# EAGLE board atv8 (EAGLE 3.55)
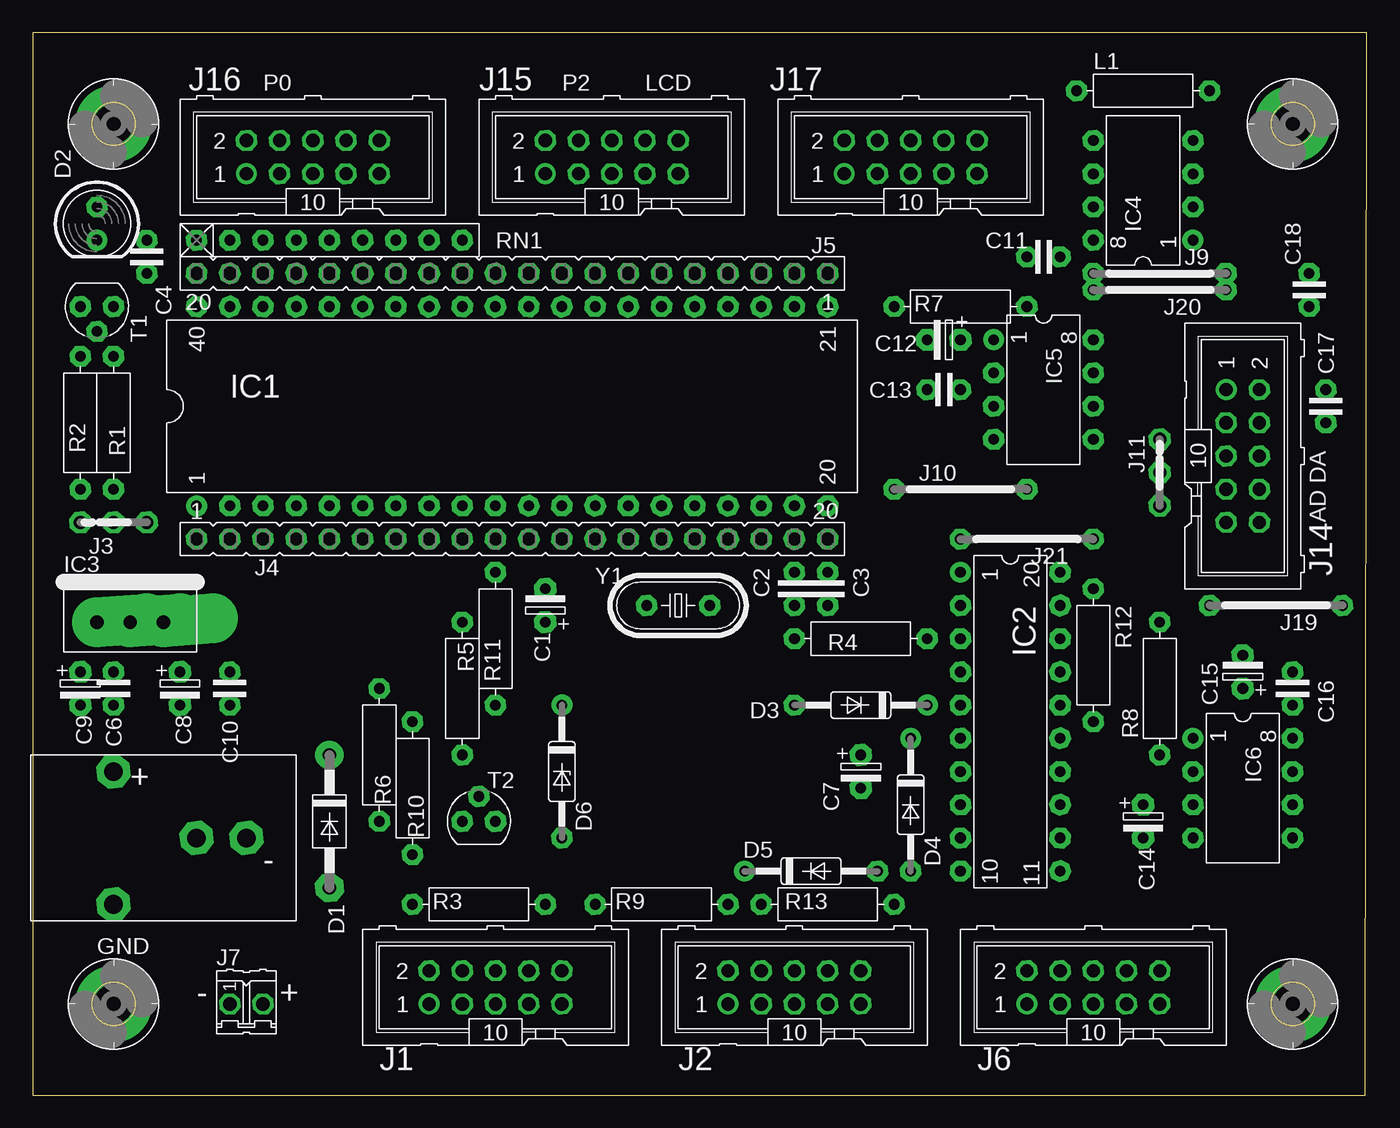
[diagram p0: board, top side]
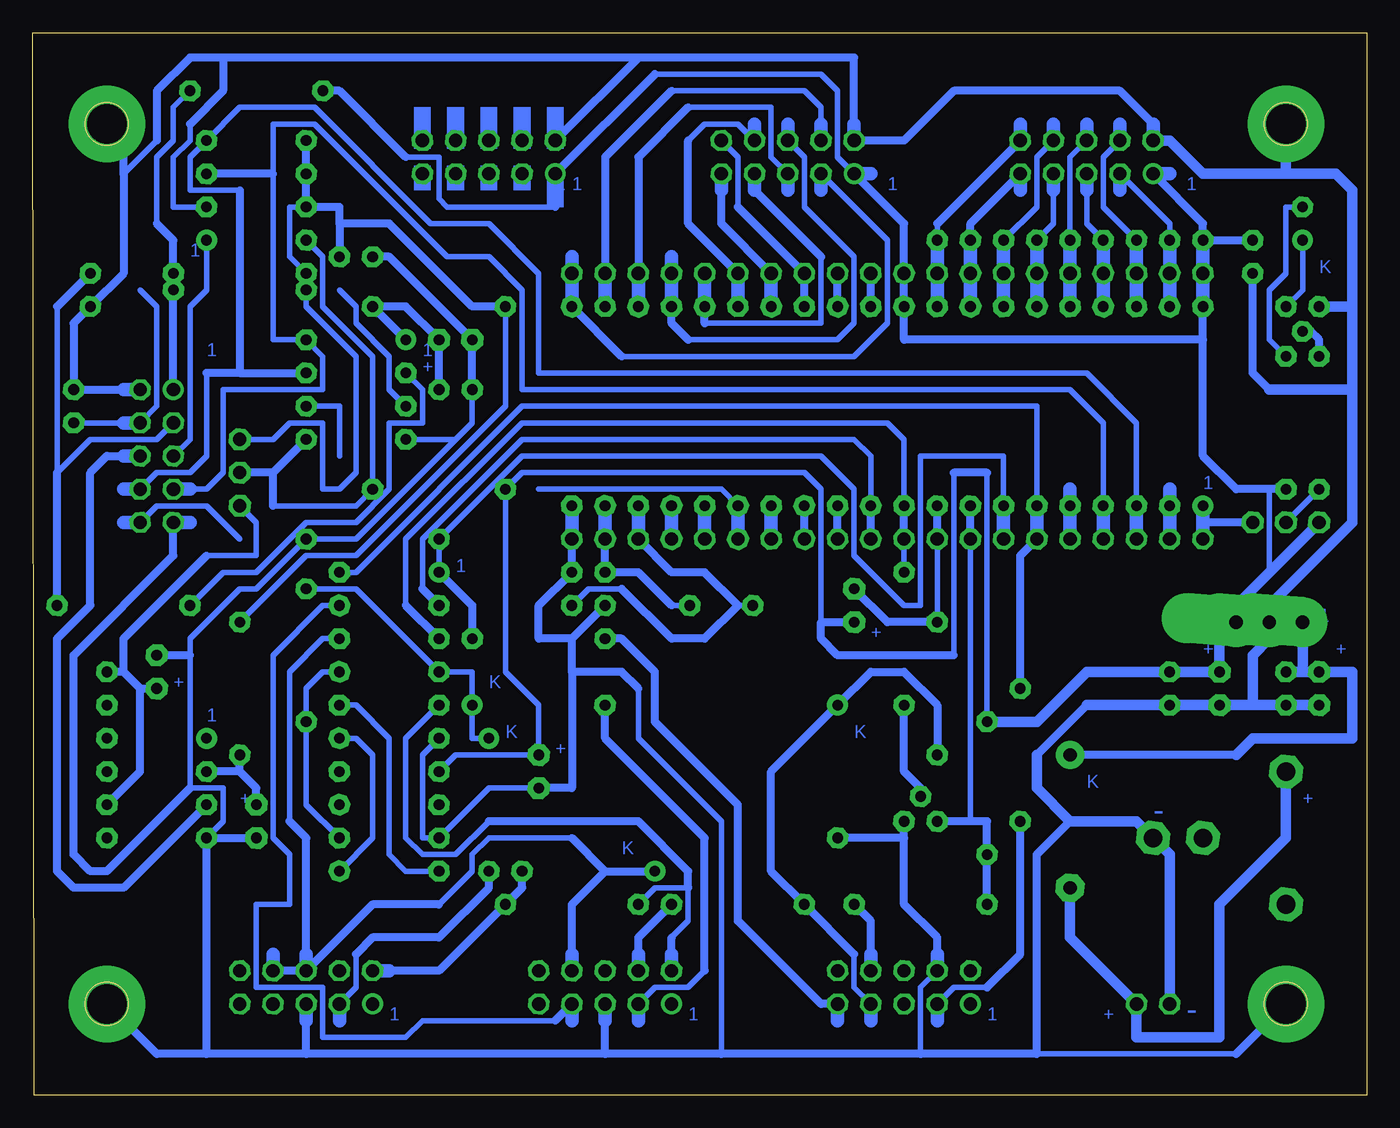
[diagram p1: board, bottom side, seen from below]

Size 102.03 x 81.27 mm. Coordinates in mm from the lower left corner, seen from the top.
Outline: 0,0 101.91,0 102.03,81.27 0,81.27 0,0
Copper layers used: Bottom

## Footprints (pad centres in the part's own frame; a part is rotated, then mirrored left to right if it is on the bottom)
-2,5 = drill 0.813 pad 1.676 octagon:  -1.27,0;  1.27,0
2,5 = drill 0.813 pad 1.6 octagon:  -1.27,0;  1.27,0
41-10 = drill 1.016 pad 2.159 octagon:  5.08,0 | drill 1.016 pad 2.159 round:  -5.08,0
D5 = drill 0.813 pad 1.6 octagon:  -1.27,0 | drill 0.813 pad 1.6 round:  1.27,0
35-10 = drill 0.813 pad 1.6 round:  -5.08,0 | drill 0.813 pad 1.6 octagon:  5.08,0
35Z10 = drill 0.813 pad 1.6 round:  -5.08,0 | drill 0.813 pad 1.6 octagon:  5.08,0
L40 = drill 0.813 pad 1.6 round:  -24.13,-7.62 | drill 0.813 pad 1.6 octagon:  -21.59,-7.62;  -19.05,-7.62;  -16.51,-7.62;  -13.97,-7.62;  -11.43,-7.62;  -8.89,-7.62;  -6.35,-7.62;  -3.81,-7.62;  -1.27,-7.62;  1.27,-7.62;  3.81,-7.62;  6.35,-7.62;  8.89,-7.62;  11.43,-7.62;  13.97,-7.62;  16.51,-7.62;  19.05,-7.62;  21.59,-7.62;  24.13,-7.62;  24.13,7.62;  21.59,7.62;  19.05,7.62;  16.51,7.62;  13.97,7.62;  11.43,7.62;  8.89,7.62;  6.35,7.62;  3.81,7.62;  1.27,7.62;  -1.27,7.62;  -3.81,7.62;  -6.35,7.62;  -8.89,7.62;  -11.43,7.62;  -13.97,7.62;  -16.51,7.62;  -19.05,7.62;  -21.59,7.62;  -24.13,7.62
L20 = drill 0.813 pad 1.6 round:  -11.43,-3.81 | drill 0.813 pad 1.6 octagon:  -8.89,-3.81;  -6.35,-3.81;  -3.81,-3.81;  -1.27,-3.81;  1.27,-3.81;  3.81,-3.81;  6.35,-3.81;  8.89,-3.81;  11.43,-3.81;  11.43,3.81;  8.89,3.81;  6.35,3.81;  3.81,3.81;  1.27,3.81;  -1.27,3.81;  -3.81,3.81;  -6.35,3.81;  -8.89,3.81;  -11.43,3.81
220 = drill 1.016 pad 3.81 offset:  -2.54,0;  0,0;  2.54,0
L08 = drill 0.813 pad 1.6 round:  -3.81,-3.81 | drill 0.813 pad 1.6 octagon:  -1.27,-3.81;  1.27,-3.81;  3.81,-3.81;  3.81,3.81;  1.27,3.81;  -1.27,3.81;  -3.81,3.81
10 = drill 1.016 pad 1.6 round:  -5.08,-1.27 | drill 1.016 pad 1.6 octagon:  -5.08,1.27;  -2.54,-1.27;  -2.54,1.27;  0,-1.27;  0,1.27;  2.54,-1.27;  2.54,1.27;  5.08,-1.27;  5.08,1.27
C = drill 1.016 pad 1.676 octagon:  -5.08,0;  -2.54,0;  0,0
20 = drill 1.016 pad 1.6 octagon:  -24.13,0;  -21.59,0;  -19.05,0;  -16.51,0;  -13.97,0;  -11.43,0;  -8.89,0;  -6.35,0;  -3.81,0;  -1.27,0;  1.27,0;  3.81,0;  6.35,0;  8.89,0;  11.43,0;  13.97,0;  16.51,0;  19.05,0;  21.59,0;  24.13,0
P = drill 1.016 pad 1.6 octagon:  -1.27,0;  1.27,0
KA1 = drill 1.422 pad 2.54 octagon:  -5.08,0;  5.08,0;  0,6.35;  0,10.16
 = drill 0.813 pad 1.6 octagon:  -5.08,0;  5.08,0
10' = drill 0.813 pad 1.6 octagon:  -5.08,0;  5.08,0
3,0-P = drill 3.023 pad 5.842 round: 0 0,0
-9 = drill 0.813 pad 1.6 octagon:  -10.16,0;  -7.62,0;  -5.08,0;  -2.54,0;  0,0;  2.54,0;  5.08,0;  7.62,0;  10.16,0
T54A = drill 0.813 pad 1.6 octagon:  -1.27,0;  0,1.905;  1.27,0
49U-V = drill 0.813 pad 1.6 octagon:  -2.413,0;  2.413,0

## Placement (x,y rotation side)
C1  1u/6.3  [-2,5]  39.2,37.46 90 top
C2  33p  [2,5]  58.26,38.73 90 top
C3  33p  [2,5]  60.8,38.73 90 top
C4  100n  [2,5]  8.72,64.13 90 top
C6  100n  [2,5]  6.19,31.11 90 top
C7  1u/6.3  [-2,5]  63.34,24.76 270 top
C8  4.7u/6.3  [-2,5]  11.27,31.11 270 top
C9  100u/35  [-2,5]  3.65,31.11 270 top
C10  100n  [2,5]  15.07,31.11 90 top
C11  100n  [2,5]  77.31,64.13 0 top
C12  1u/6.3  [-2,5]  69.69,57.78 180 top
C13  100n  [2,5]  69.69,53.97 0 top
C14  100u/35  [-2,5]  84.92,20.95 270 top
C15  4u7/6.3  [-2,5]  92.55,32.38 90 top
C16  47n  [2,5]  96.36,31.11 270 top
C17  100n  [2,5]  98.89,52.7 270 top
C18  100n  [2,5]  97.62,61.59 90 top
D1  1N4001  [41-10]  22.7,20.95 270 top
D2  LED5mm,grn  [D5]  4.92,66.67 270 top
D3  1N4148  [35-10]  63.34,29.84 180 top
D4  1N4148  [35-10]  67.14,22.22 270 top
D5  1N4148  [35-10]  59.52,17.14 0 top
D6  BZX4V7  [35Z10]  40.48,24.76 270 top
IC1  AT89C8252  [L40]  36.66,52.7 0 top
IC2  MAX233CPP  [L20]  74.77,28.57 270 top
IC3  7805  [220]  7.46,36.19 0 top
IC4  MAX517ACPA  [L08]  84.92,69.21 90 top
IC5  MAX144ACP  [L08]  77.31,53.97 270 top
IC6  MAX874CPA  [L08]  92.55,23.49 270 top
J1  10pol para  [10]  35.4,8.25 0 top
J2  10pol ser.  [10]  58.26,8.25 0 top
J3  Jumper  [C]  3.65,43.81 180 top
J4  20pol  [20]  36.66,42.54 0 top
J5  20pol  [20]  36.66,62.86 180 top
J6  10pol. ser. ex  [10]  81.11,8.25 0 top
J7  Buchse  [P]  16.34,6.98 0 top
J8  Bu2  [KA1]  6.19,19.68 270 top
J9  J10  []  86.19,62.86 0 top
J10  J15  []  70.95,46.35 0 top
J11  Jumper  [C]  86.19,50.16 90 top
J14  10pol/Wanne  [10]  92.55,48.89 270 top
J15  10pol/Wanne  [10]  44.28,71.75 0 top
J16  10pol/Wanne  [10]  21.43,71.75 0 top
J17  10pol/Wanne  [10]  67.14,71.75 0 top
J19  J10  []  95.08,37.46 180 top
J20  J15  []  86.19,61.59 180 top
J21  J20  []  76.03,42.54 180 top
L1  3u3  [10']  84.92,76.83 0 top
PAD1  BO3,0P  [3,0-P]  96.36,6.98 0 top
PAD2  BO3,0P  [3,0-P]  6.19,6.98 0 top
PAD3  BO3,0P  [3,0-P]  96.36,74.29 0 top
PAD4  BO3,0P  [3,0-P]  6.19,74.29 180 top
R1  470  [10']  6.19,51.43 90 top
R2  10K  [10']  3.65,51.43 270 top
R3  330  [10']  34.12,14.6 180 top
R4  330  [10']  63.34,34.92 0 top
R5  330  [10']  32.86,31.11 90 top
R6  330  [10']  26.5,26.03 90 top
R7  10  [10']  70.95,60.32 180 top
R8  150  [10']  86.19,31.11 90 top
R9  1K  [10']  48.09,14.6 180 top
R10  1K  [10']  29.05,23.49 90 top
R11  10K  [10']  35.4,34.92 270 top
R12  2K7  [10']  81.11,33.65 270 top
R13  6K8  [10']  60.8,14.6 180 top
RN1  22Kx8  [-9]  22.7,65.4 0 top
T1  BC547C  [T54A]  4.92,60.32 180 top
T2  BC547C  [T54A]  34.12,20.95 0 top
Y1  22,1184MHz  [49U-V]  49.37,37.46 0 top

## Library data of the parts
C1-C4 C6-C18 L1 R1-R13 RN1 = DISCRETE
D1 D3-D6 = DIODE
D2 = LED
IC1 = INTEL
IC2 IC4-IC6 = maximnew
IC3 = LINEAR
J1 J2 J6 J14-J17 = CON-ML
J3 J9-J11 J19-J21 = JUMPER-r
J4 J5 = CON-LSTA
J7 J8 = CONQUICK
PAD1-PAD4 = HOLES
T1 T2 = TRANS-SM
Y1 = QUARTZ

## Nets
+5V: J9. J14. L1.
GND: C2. C3. C4. C6. C7. C8. C9. C10. C11. C12. C13. C14. C15. C17. C18. D6. IC1. IC2. IC3. IC4. IC5. IC6. J1. J2. J4. J6. J7. J8. J14. J15. J16. J17. PAD1.0 PAD2.0 PAD3.0 PAD4.0 T1. T2.
J8: D6. J1. R5. R9.
N$1: C2. IC1. J4. Y1.
N$2: C3. IC1. J4. Y1.
N$3: IC1. J5.
N$4: IC1. J5.
N$5: IC2.
N$6: IC2.
N$7: D2. R1.
N$8: IC2. R12.
N$9: IC5. J19.
N$10: IC4. IC5. J11.
N$11: J14. J21.
N$12: D3. D4. IC2. R12.
N$13: J1. R6.
N$14: J1. R3.
N$15: IC5. J20.
N$16: D2. T1.
N$17: R2. T1.
N$18: J3. R2.
N$19: IC2. J2. R13.
N$20: C17. J14. J20.
N$21: J1. R4.
N$22: C12. C13. IC5. R7.
N$23: D1. J7. J8.
N$24: C6. C9. D1. IC3.
N$25: D5. J6. R13.
N$26: C14. IC6. R8.
N$28: C18. J14. J19.
N$29: C15. C16. IC6. J11.
N$30: C16.
N$31: C11. IC4. J9. J11. R7. R8.
N$32: IC6. J14.
N$33: IC5. J10.
N$34: IC6.
N$35: IC4. J14.
N$36: IC2. J2.
N$37: D4. J6.
N$38: J2. R9.
N$39: R11. T2.
N$40: D3. J2.
N$41: D5. IC2. J2. J6.
P00: IC1. J5. J16. RN1.
P01: IC1. J5. J16. RN1.
P02: IC1. J5. J16. RN1.
P03: IC1. J5. J16. RN1.
P04: IC1. J5. J16. RN1.
P05: IC1. J5. J16. RN1.
P06: IC1. J5. J16. RN1.
P07: IC1. J5. J16. RN1.
P10: IC1. J3. J4.
P11: IC1. J4.
P12: IC1. IC4. IC5. J4. J14.
P13: IC1. IC4. IC5. J4. J14.
P14: IC1. J4.
P15: IC1. IC2. J4. R6.
P16: IC1. IC2. J4. R4.
P17: IC1. J4. R3. R10. T2.
P20: IC1. J5. J15.
P21: IC1. J5. J15.
P22: IC1. J5. J15.
P23: IC1. J5. J15.
P24: IC1. J5. J15.
P25: IC1. J5. J15.
P26: IC1. J5. J15.
P27: IC1. J5. J15.
P30: IC1. IC2. J4. R11.
P31: IC1. IC2. J4.
P32: IC1. J4.
P33: IC1. J4.
P34: IC1. J4.
P35: IC1. J4. J10.
P36: IC1. J4.
P37: IC1. J4.
RST: C1. IC1. J4. R5.
VCC: C1. C4. C7. C8. C10. IC1. IC2. IC3. J3. J5. J15. J16. J17. J21. L1. R1. R10. RN1.

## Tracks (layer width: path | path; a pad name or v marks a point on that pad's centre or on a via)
+5V
  Bottom 0.406: 92.55,66.67 92.55,71.75 91.28,73.02 91.28,75.56 L1.
  Bottom 0.61: 92.55,66.67 91.28,65.4 J9. 91.28,53.97
GND
  Bottom 0.406: 68.42,53.97 68.42,51.43 69.69,50.16 | 70.95,27.3 72.22,26.03 72.22,19.68 70.95,19.68 67.14,23.49 C7. | 32.86,9.52 34.12,8.25 34.12,3.17 | 10,3.17 25.23,3.17 | 92.55,73.02 95.08,70.48 | 88.73,67.94 91.28,67.94 91.28,71.75 90,73.02 90,74.29 | 55.72,31.11 55.72,27.3 49.37,20.95 49.37,3.17 | 88.73,19.68 87.47,20.95 87.47,23.49 90,23.49 90,33.65 90,34.92 86.19,38.73 84.92,38.73 81.11,42.54 77.31,42.54 69.69,50.16 | 69.69,50.16 73.5,50.16
  Bottom 0.61: C14. 88.73,19.68 88.73,3.17 | 81.11,3.17 88.73,3.17 | 68.42,53.97 C12. 74.77,64.13 76.03,64.13 | 91.28,43.81 91.28,41.27 98.89,33.65 98.89,18.41 97.62,17.14 96.36,17.14 90,23.49 | 32.86,10.79 32.86,12.06 35.4,14.6 35.4,19.68 | J4. C3. 63.34,37.46 63.34,34.92 60.8,34.92 | C7. 60.8,23.49 60.8,32.38 | 60.8,34.92 58.26,37.46 | 60.8,32.38 60.8,34.92 | 39.2,74.29 39.2,79.37 55.72,79.37 | 55.72,79.37 62.06,73.02 | 7.46,53.97 8.72,55.24 8.72,62.86 | 39.2,73.02 35.4,73.02 31.59,76.83 18.89,76.83 16.34,74.29 | 81.11,3.17 81.11,5.71 | 58.26,3.17 49.37,3.17 34.12,3.17 25.23,3.17 25.23,18.41 22.7,20.95 | 58.26,3.17 81.11,3.17 | 25.23,26.03 21.43,29.84 | PAD2.0 10,3.17 | 95.08,53.97 98.89,53.97 98.89,59.05 97.62,60.32 95.08,62.86 95.08,70.48 95.08,74.29 PAD3.0 | 92.55,73.02 92.55,76.83 90,79.37 87.47,79.37 | 55.72,79.37 87.47,79.37 | 35.4,19.68 T2. | 35.4,19.68 D6. | 87.47,79.37 87.47,76.83 90,74.29 | 58.26,3.17 58.26,5.71 | 60.8,32.38 56.98,32.38 55.72,31.11 | 90,33.65 C15. | 88.73,3.17 92.55,3.17 PAD1.0
  Bottom 0.813: C9. 6.19,29.84 8.72,29.84 | 8.72,29.84 C8. 15.07,29.84 21.43,29.84 | 8.72,29.84 8.72,33.65 7.46,34.92 7.46,36.19 7.46,37.46 1.1,43.81 1.1,53.97 | 15.07,6.98 15.07,18.41 J8. 17.62,20.95 22.7,20.95 25.23,23.49 25.23,26.03 | 1.1,60.32 T1. | 1.1,53.97 1.1,60.32 | 1.1,53.97 7.46,53.97 | 16.34,73.02 15.07,73.02 12.54,70.48 6.19,70.48 | 6.19,70.48 2.38,70.48 1.1,69.21 1.1,60.32 | 6.19,70.48 PAD4.0
  Bottom 1.016: J4. 60.8,45.08 | 16.34,73.02 16.34,74.29 | 39.2,73.02 39.2,74.29 | 95.08,53.97 93.81,53.97 | 91.28,43.81 90,43.81 | 81.11,5.71 81.11,6.98 | 58.26,5.71 58.26,6.98 | 32.86,9.52 32.86,10.79
J8
  Bottom 0.406: 37.94,6.98 39.2,8.25 39.2,10.79
  Bottom 0.61: 32.86,26.03 32.86,29.84 35.4,32.38 37.94,32.38 40.48,29.84 45.55,24.76 45.55,17.14 R9. 39.2,10.79
  Bottom 1.016: 37.94,5.71 37.94,6.98
N$1
  Bottom 0.406: Y1. 53.17,37.46
  Bottom 0.61: 58.26,42.54 C2. 55.72,40 53.17,37.46
  Bottom 1.016: 58.26,42.54 58.26,45.08
N$2
  Bottom 0.406: 60.8,37.46 59.52,38.73 56.98,38.73 | 46.95,37.46 48.09,37.46
  Bottom 0.61: 55.72,42.54 53.17,40 50.63,40 48.09,37.46 50.63,34.92 53.17,34.92 56.98,38.73
  Bottom 1.016: 55.72,42.54 55.72,45.08
N$3
  Bottom 0.61: 40.48,60.32 40.48,62.86
N$4
  Bottom 0.61: 37.94,60.32 37.94,62.86
N$5
  Bottom 0.406: 78.58,17.14 76.03,19.68 76.03,26.03 77.31,27.3 78.58,27.3
N$6
  Bottom 0.406: 70.95,17.14 73.5,17.14 74.77,18.41 74.77,27.3 77.31,29.84 78.58,29.84
N$7
  Bottom 0.406: 4.92,67.94 6.19,67.94 6.19,62.86 7.46,61.59 7.46,57.78 R1.
N$8
  Bottom 0.406: 78.58,19.68 81.11,22.22 R12. 81.11,31.11 79.84,32.38 78.58,32.38
N$9
  Bottom 0.406: J19. 87.47,40 84.92,40 81.11,43.81 77.31,43.81 74.77,46.35 74.77,51.43 72.22,51.43 72.22,53.97 73.5,55.24
N$10
  Bottom 0.406: IC4. 79.84,64.13 79.84,60.32 76.03,56.51 76.03,46.35 77.31,45.08 83.66,45.08
  Bottom 0.61: 83.66,47.62 81.11,50.16 | 83.66,47.62 86.19,47.62 | 83.66,45.08 83.66,47.62
N$11
  Bottom 0.406: J14. 92.55,45.08 88.73,45.08 86.19,42.54
  Bottom 1.016: J14. 95.08,43.81
N$12
  Bottom 0.406: 81.11,38.73 77.31,38.73 70.95,32.38 68.42,32.38 68.42,29.84 68.42,27.3 67.14,27.3
N$13
  Bottom 0.406: 32.86,6.98 31.59,8.25 29.05,8.25
  Bottom 0.61: 29.05,8.25 26.5,10.79 26.5,20.95
  Bottom 1.016: 32.86,6.98 32.86,5.71
N$14
  Bottom 0.61: 37.94,10.79 37.94,13.33 39.2,14.6
  Bottom 1.016: 37.94,9.52 37.94,10.79
N$15
  Bottom 0.406: 73.5,52.7 74.77,53.97 74.77,56.51 77.31,59.05 77.31,60.32 78.58,61.59
N$16
  Bottom 0.406: 6.19,60.32 4.92,61.59 D2.
N$17
  Bottom 0.61: 4.92,58.41 4.28,58.41 3.65,57.78 3.65,56.51
N$18
  Bottom 0.406: 6.19,43.81 R2.
N$19
  Bottom 0.406: 53.17,12.06 51.91,13.33 51.91,15.87 54.45,15.87 R13. | 70.95,29.84 73.5,27.3 73.5,19.68 72.22,18.41 69.69,18.41 67.14,20.95
  Bottom 0.61: 53.17,10.79 53.17,12.06 | 67.14,20.95 55.72,20.95 51.91,17.14 51.91,15.87
  Bottom 1.016: 53.17,9.52 53.17,10.79
N$20
  Bottom 0.406: 93.81,61.59 92.55,60.32 92.55,52.7 93.81,51.43 | 95.08,51.43 C17.
  Bottom 1.016: 93.81,51.43 95.08,51.43
N$21
  Bottom 0.61: 40.48,6.98 41.74,6.98 48.09,13.33 48.09,22.22 54.45,28.57 54.45,32.38 56.98,34.92 58.26,34.92
  Bottom 1.016: 40.48,5.71 40.48,6.98
N$22
  Bottom 0.61: C13. 70.95,57.78 73.5,60.32 76.03,60.32 73.5,57.78
N$23
  Bottom 0.813: 6.19,24.76 6.19,19.68 11.27,14.6 11.27,4.44 17.62,4.44 J7. 22.7,12.06 22.7,15.87
N$24
  Bottom 0.406: 4.92,32.38 3.65,32.38 2.38,32.38
  Bottom 0.61: 10,26.03 D1.
  Bottom 0.813: 4.92,32.38 C6. | 4.92,32.38 2.38,32.38 1.1,32.38 1.1,27.3 8.72,27.3 10,26.03 | 4.92,32.38 4.92,36.19
N$25
  Bottom 0.61: 74.77,9.52 70.95,9.52 65.88,14.6 64.6,15.87 D5.
  Bottom 1.016: 74.77,9.52 76.03,9.52
N$26
  Bottom 0.61: 86.19,24.76 88.73,24.76 | 86.19,24.76 86.19,26.03 | 84.92,22.22 84.92,23.49 86.19,24.76
N$28
  Bottom 0.406: 91.28,51.43 92.55,50.16 97.62,50.16 100.17,47.62 100.17,60.32
  Bottom 0.61: 100.17,37.46 100.17,47.62 | 100.17,60.32 C18.
N$29
  Bottom 0.406: 88.73,41.27 84.92,41.27 84.92,43.81 86.19,45.08
  Bottom 0.61: 96.36,22.22 93.81,24.76 93.81,31.11 | 93.81,31.11 95.08,32.38 | 95.08,32.38 96.36,32.38 | 93.81,31.11 92.55,31.11 | 88.73,41.27 95.08,34.92 95.08,32.38
N$31
  Bottom 0.406: 81.11,67.94 82.39,67.94 82.39,64.13 81.11,62.86 81.11,60.32 77.31,56.51 77.31,47.62 78.58,46.35 79.84,46.35 79.84,51.43 82.39,51.43 83.66,50.16 J11. | R8. 81.11,41.27 77.31,41.27 65.88,52.7 R7.
  Bottom 0.61: 78.58,66.67 74.77,66.67 68.42,60.32 R7. | 78.58,66.67 C11. | 78.58,66.67 78.58,67.94 81.11,67.94 81.11,70.48 81.11,73.02
N$32
  Bottom 0.61: 95.08,48.89 96.36,48.89 97.62,47.62 97.62,37.46 100.17,34.92 100.17,17.14 98.89,15.87 95.08,15.87 88.73,22.22
  Bottom 1.016: 95.08,48.89 93.81,48.89
N$33
  Bottom 0.406: 81.11,52.7 78.58,52.7 78.58,48.89
N$35
  Bottom 0.406: 91.28,48.89 90,50.16 90,60.32 88.73,61.59 88.73,65.4
N$36
  Bottom 0.406: 62.06,5.71 72.22,5.71 73.5,4.44 79.84,4.44 79.84,8.25 84.92,8.25 84.92,14.6 82.39,14.6 82.39,18.41 83.66,19.68 83.66,33.65 79.84,37.46 78.58,37.46
  Bottom 0.61: 60.8,6.98 62.06,5.71
  Bottom 1.016: 60.8,5.71 60.8,6.98
N$37
  Bottom 0.406: 78.58,6.98 77.31,8.25 77.31,10.79
  Bottom 0.61: 77.31,10.79 76.03,12.06 70.95,12.06 67.14,15.87 D4.
  Bottom 1.016: 78.58,6.98 78.58,5.71
N$38
  Bottom 0.61: 55.72,10.79 55.72,12.06 53.17,14.6
  Bottom 1.016: 55.72,9.52 55.72,10.79
N$39
  Bottom 0.61: R11. 35.4,24.76 34.12,23.49 34.12,22.86
N$40
  Bottom 0.406: 55.72,6.98 54.45,8.25 51.91,8.25 50.63,9.52
  Bottom 0.61: 50.63,9.52 50.63,19.68 58.26,27.3 D3.
  Bottom 1.016: 55.72,6.98 55.72,5.71
N$41
  Bottom 0.406: 70.95,14.6 68.42,17.14 68.42,18.41 67.14,19.68 60.8,19.68 | 78.58,34.92 79.84,34.92 82.39,32.38 82.39,20.95
  Bottom 0.61: 83.66,9.52 81.11,9.52 76.03,14.6 70.95,14.6 | 60.8,10.79 60.8,14.6 58.26,17.14 | 82.39,20.95 81.11,19.68 81.11,10.79 | 58.26,17.14 54.45,17.14 | 58.26,17.14 60.8,19.68
  Bottom 1.016: 83.66,9.52 83.66,10.79 | 81.11,9.52 81.11,10.79 | 60.8,9.52 60.8,10.79
P00
  Bottom 0.406: 18.89,70.48 15.07,66.67 15.07,65.4
  Bottom 1.016: 15.07,60.32 15.07,62.86 15.07,65.4 | 18.89,70.48 18.89,69.21
P01
  Bottom 0.406: 18.89,73.02 20.16,71.75 20.16,67.94 17.62,65.4
  Bottom 1.016: 17.62,60.32 17.62,62.86 17.62,65.4 | 18.89,73.02 18.89,74.29
P02
  Bottom 0.406: 21.43,69.21 21.43,66.67 20.16,65.4
  Bottom 1.016: 20.16,60.32 20.16,62.86 20.16,65.4 | 21.43,69.21 21.43,70.48
P03
  Bottom 0.406: 21.43,73.02 22.7,71.75 22.7,65.4
  Bottom 1.016: 22.7,60.32 22.7,62.86 22.7,65.4 | 21.43,73.02 21.43,74.29
P04
  Bottom 0.406: 23.96,69.21 23.96,66.67 25.23,65.4
  Bottom 1.016: 25.23,60.32 25.23,62.86 25.23,65.4 | 23.96,69.21 23.96,70.48
P05
  Bottom 0.406: 23.96,73.02 25.23,71.75 25.23,67.94 27.77,65.4
  Bottom 1.016: 27.77,60.32 27.77,62.86 27.77,65.4 | 23.96,73.02 23.96,74.29
P06
  Bottom 0.61: 26.5,70.48 30.32,66.67 30.32,65.4
  Bottom 1.016: 30.32,60.32 30.32,62.86 30.32,65.4 | 26.5,70.48 26.5,69.21
P07
  Bottom 0.406: RN1. 32.86,66.67
  Bottom 0.61: 32.86,66.67 J16.
  Bottom 1.016: 32.86,60.32 32.86,62.86 RN1. | J16. 26.5,74.29
P10
  Bottom 0.61: 8.72,43.81 12.54,43.81
  Bottom 1.016: 12.54,45.08 12.54,43.81 12.54,42.54
P11
  Bottom 1.016: 15.07,42.54 15.07,45.08 15.07,46.35
P12
  Bottom 0.406: 86.19,69.21 90,69.21 90,71.75 88.73,73.02 86.19,75.56 80.48,75.56 71.59,66.67 67.14,66.67 63.34,62.86 63.34,55.24 21.43,55.24 17.62,51.43 17.62,45.08 | 93.81,46.35 92.55,47.62 90,47.62 88.73,48.89 88.73,55.24
  Bottom 0.61: 86.19,69.21 86.19,55.24 | 86.19,55.24 88.73,55.24 | 86.19,55.24 81.11,55.24
  Bottom 1.016: 17.62,42.54 17.62,45.08 | 93.81,46.35 95.08,46.35
P13
  Bottom 0.406: 20.16,45.08 20.16,51.43 22.7,53.97 64.6,53.97 64.6,61.59 67.14,64.13 70.32,64.13 80.48,74.29 83.66,74.29 83.66,70.48 83.66,57.78 IC5. 79.84,56.51 79.84,53.97 87.47,53.97 87.47,47.62 88.73,46.35 90,46.35
  Bottom 0.61: 83.66,70.48 88.73,70.48
  Bottom 1.016: 20.16,42.54 20.16,45.08 | 90,46.35 91.28,46.35
P14
  Bottom 1.016: 22.7,42.54 22.7,45.08 22.7,46.35
P15
  Bottom 0.406: IC2. 77.31,40 64.6,52.7 25.23,52.7 25.23,45.08
  Bottom 0.61: R6. 26.5,41.27 25.23,42.54
  Bottom 1.016: 25.23,42.54 25.23,45.08
P16
  Bottom 0.406: 27.77,42.54 27.77,45.08 27.77,48.89 34.12,48.89 34.12,37.46 35.4,37.46 39.2,41.27 39.2,46.35 41.74,48.89 64.6,48.89 70.95,42.54 70.95,40
  Bottom 0.61: R4. 68.42,37.46 70.95,40
  Bottom 1.016: 27.77,42.54 27.77,45.08
P17
  Bottom 0.406: 30.32,20.95 30.32,42.54
  Bottom 0.61: 30.32,42.54 30.32,45.08 | R3. 29.05,18.41 29.05,20.95 30.32,20.95 32.86,20.95
P20
  Bottom 0.406: 41.74,70.48 36.66,65.4 36.66,59.05 39.2,56.51 56.98,56.51
  Bottom 0.61: 56.98,56.51 60.8,60.32
  Bottom 1.016: 60.8,60.32 60.8,62.86 60.8,64.13 | 41.74,70.48 41.74,69.21
P21
  Bottom 0.406: 41.74,73.02 41.74,75.56 43.02,76.83 53.17,76.83
  Bottom 0.61: 53.17,76.83 58.26,71.75 58.26,62.86
  Bottom 1.016: 58.26,62.86 58.26,60.32 | 41.74,73.02 41.74,74.29
P22
  Bottom 0.406: 44.28,70.48 45.55,71.75 45.55,75.56 51.91,75.56
  Bottom 0.61: 51.91,75.56 55.72,71.75 55.72,62.86
  Bottom 1.016: 55.72,62.86 55.72,60.32 | 44.28,69.21 44.28,70.48
P23
  Bottom 0.406: 44.28,73.02 43.02,71.75 43.02,67.94 39.2,64.13 39.2,59.05 40.48,57.78 51.91,57.78
  Bottom 0.61: 51.91,57.78 53.17,59.05 53.17,60.32
  Bottom 1.016: 53.17,60.32 53.17,62.86 53.17,64.13 | 44.28,73.02 44.28,74.29
P24
  Bottom 0.406: 41.74,64.13 41.74,59.05 50.63,59.05
  Bottom 0.61: 41.74,64.13 46.83,69.21 | 50.63,59.05 50.63,60.32
  Bottom 1.016: 50.63,60.32 50.63,62.86 | 46.83,69.21 46.83,70.48
P25
  Bottom 0.406: 46.83,73.02 48.09,74.29 50.63,74.29 51.91,73.02
  Bottom 0.61: 51.91,73.02 51.91,66.67 48.09,62.86
  Bottom 1.016: 48.09,60.32 48.09,62.86 | 46.83,73.02 46.83,74.29
P26
  Bottom 0.61: 49.37,69.21 49.37,66.67 45.55,62.86
  Bottom 1.016: 45.55,60.32 45.55,62.86 | 49.37,69.21 49.37,70.48
P27
  Bottom 0.406: J15. 48.09,71.75 48.09,67.94
  Bottom 0.61: 43.02,60.32 43.02,62.86 48.09,67.94
P30
  Bottom 0.406: 35.4,40 35.4,42.54 | 73.5,37.46 73.5,42.54 64.6,51.43 36.66,51.43 35.4,50.16 35.4,45.08
  Bottom 0.61: 35.4,42.54 35.4,45.08 | 73.5,37.46 70.95,34.92
P31
  Bottom 0.406: 72.22,38.73 72.22,42.54 64.6,50.16 39.2,50.16 37.94,48.89 37.94,45.08
  Bottom 0.61: 37.94,42.54 37.94,45.08 | 72.22,38.73 70.95,37.46
P32
  Bottom 0.61: 40.48,42.54 40.48,45.08
P33
  Bottom 0.61: 43.02,42.54 43.02,45.08
P34
  Bottom 1.016: 45.55,42.54 45.55,45.08
P35
  Bottom 0.406: 48.09,45.08 49.37,46.35 63.34,46.35
  Bottom 1.016: 48.09,42.54 48.09,45.08
P36
  Bottom 1.016: 50.63,42.54 50.63,45.08
P37
  Bottom 1.016: 53.17,42.54 53.17,45.08
RST
  Bottom 0.406: R5. 32.86,42.54
  Bottom 0.61: 32.86,42.54 32.86,45.08 | R5. 36.66,36.19 C1.
VCC
  Bottom 0.406: 7.46,40 7.46,46.35 6.19,46.35 | 62.06,67.94 70.32,67.94 70.95,68.58 70.95,71.75 73.5,71.75 | 70.95,24.76 69.69,26.03 63.34,26.03 63.34,29.84 65.88,32.38 65.88,42.54 65.88,46.35 64.6,47.62 43.02,47.62 41.74,46.35 41.74,36.19 | 31.59,47.62 31.59,33.65 | R10. 29.05,47.62 | 39.2,70.48 40.48,71.75 40.48,76.83 41.74,78.1 54.45,78.1
  Bottom 0.61: 12.54,57.78 IC1. | 6.19,46.35 10,46.35 12.54,48.89 12.54,57.78 | 62.06,67.94 62.06,70.48 54.45,78.1 | 39.2,70.48 35.4,66.67 35.4,60.32 35.4,57.78 12.54,57.78 | C4. 12.54,65.4 12.54,66.67 16.34,70.48 | 31.59,33.65 40.48,33.65 41.74,34.92 41.74,36.19 39.2,36.19 | 29.05,47.62 31.59,47.62 | 73.5,71.75 78.58,76.83 79.84,76.83
  Bottom 0.813: J3. 7.46,40 10,37.46 IC3. 11.27,34.92 11.27,32.38 C10. 21.43,32.38 25.23,28.57 R10.
  Bottom 1.016: IC1. J5. 12.54,65.4 | 16.34,70.48 15.07,70.48 | 39.2,70.48 37.94,70.48
(copper drawn outside any net)
  shapes: Bottom area x10

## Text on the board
Bottom: 1 | 1 | 1 | 1 | 1 | K | 1 | 1 | + | 1 | 1 | 1 | + | + | + | K | + | 1 | K | K | + | K | + | + | - | K | - | + | 1 | 1 | 1
tPlace: + | - | - | +
tNames: P0 | P2 | LCD | AD DA | GND
tValues: LED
